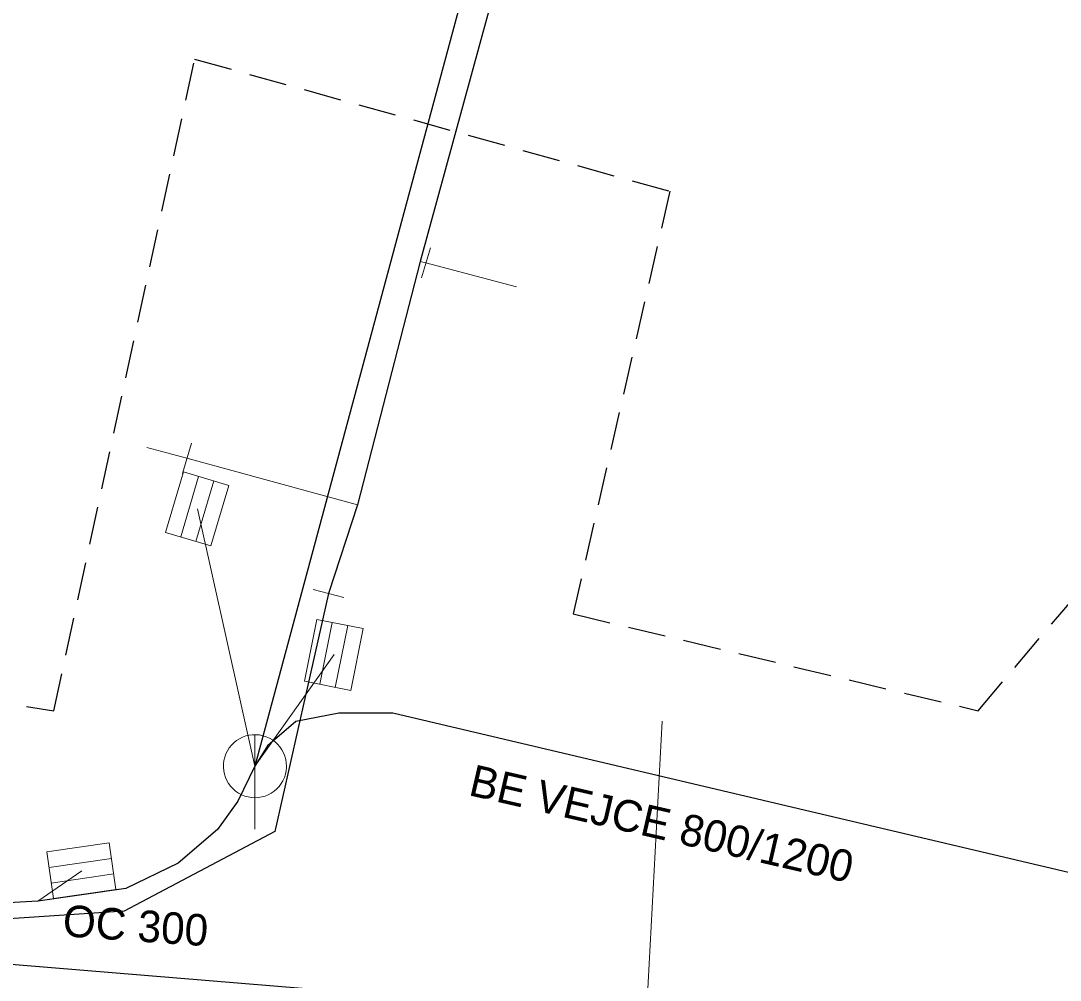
# Model space of a CAD drawing. Extents: x -725643 to -725418, y -978375 to -978221.
# Drawn here: x -725534.94 to -725501.98, y -978341.11 to -978310.7 of the extents above; entities that cross this region are included whole.
import ezdxf

# ---------------------------------------------------------------- set-up
doc = ezdxf.new("R2010")
doc.units = 0
doc.header["$LTSCALE"] = 0.4
doc.linetypes.add('MEDIUM_DASHED', pattern=[4.5, 3, -1.5])
doc.layers.add('1', color=7, linetype='Continuous')
for name, color, linetype, lineweight in [('11', 7, 'Continuous', 13), ('13', 7, 'Continuous', 13), ('14', 7, 'Continuous', 25), ('17', 7, 'Continuous', 25), ('22', 7, 'Continuous', 13), ('34', 7, 'Continuous', 13), ('63', 7, 'MEDIUM_DASHED', 25)]:
    doc.layers.add(name, color=color, linetype=linetype, lineweight=lineweight)

msp = doc.modelspace()

# ---------------------------------------------------------------- linework, layer by layer
at = {"layer": '11'}
for p, q in [((-725529.334, -978326.168), (-725527.513, -978334.331)), ((-725525.004, -978330.795), (-725527.513, -978334.331)), ((-725533.005, -978337.649), (-725534.392, -978338.607))]:
    msp.add_line(p, q, dxfattribs=at)
at = {"layer": '13'}
for p, q in [((-725522.092, -978318.376), (-725519.223, -978319.135)), ((-725529.668, -978324.571), (-725530.941, -978324.232)), ((-725524.258, -978326.048), (-725529.668, -978324.571)), ((-725515.079, -978341.78), (-725514.594, -978332.899))]:
    msp.add_line(p, q, dxfattribs=at)
at = {"layer": '14'}
msp.add_line((-725514.39, -978285.573), (-725527.514, -978334.332), dxfattribs=at)
at = {"layer": '14', "lineweight": 13}
msp.add_line((-725522.274, -978318.329), (-725522.092, -978318.376), dxfattribs=at)
at = {"layer": '14'}
for points in [[(-725527.513, -978334.331), (-725528.055, -978335.436), (-725528.703, -978336.338), (-725529.951, -978337.403), (-725531.603, -978338.206), (-725534.392, -978338.607), (-725536.813, -978338.747), (-725553.081, -978337.228), (-725592.702, -978330.168)], [(-725500.956, -978337.877), (-725523.136, -978332.647), (-725524.855, -978332.647), (-725526.213, -978332.919), (-725527.118, -978333.688), (-725527.513, -978334.331)]]:
    msp.add_lwpolyline(points, dxfattribs=at)
at = {"layer": '17'}
for points in [[(-725501.997, -978253.052), (-725503.357, -978256.875), (-725505.252, -978262.592), (-725505.556, -978263.438), (-725508.484, -978272.373), (-725509.739, -978276.131), (-725510.554, -978278.613), (-725510.695, -978279.061), (-725511.728, -978282.605), (-725512.877, -978286.761), (-725514.173, -978290.473), (-725514.784, -978292.403), (-725516.449, -978298.217), (-725517.002, -978300.824), (-725519.502, -978308.238), (-725519.585, -978308.511), (-725522.274, -978318.329), (-725524.258, -978326.048), (-725525.18, -978328.858)], [(-725525.18, -978328.858), (-725526.883, -978336.403), (-725531.655, -978338.927), (-725545.003, -978339.812)], [(-725516.432, -978342.059), (-725524.989, -978341.46), (-725545.003, -978339.812), (-725548.553, -978340.172), (-725550.989, -978339.387)]]:
    msp.add_lwpolyline(points, dxfattribs=at)
at = {"layer": '22'}
for p, q in [((-725529.865, -978327.065), (-725529.3, -978325.146)), ((-725529.386, -978327.206), (-725528.82, -978325.288)), ((-725525.453, -978331.735), (-725525.061, -978329.774)), ((-725524.963, -978331.834), (-725524.571, -978329.873)), ((-725527.513, -978336.331), (-725527.512, -978333.331)), ((-725534.042, -978337.54), (-725532.062, -978337.253)), ((-725533.97, -978338.034), (-725531.991, -978337.748))]:
    msp.add_line(p, q, dxfattribs=at)
for points in [[(-725530.345, -978326.924), (-725529.78, -978325.005), (-725528.341, -978325.429), (-725528.906, -978327.347)], [(-725525.944, -978331.637), (-725525.551, -978329.676), (-725524.08, -978329.971), (-725524.473, -978331.932)], [(-725526.513, -978334.331), (-725526.518, -978334.222), (-725526.536, -978334.114), (-725526.566, -978334.008), (-725526.606, -978333.907), (-725526.658, -978333.81), (-725526.72, -978333.72), (-725526.792, -978333.637), (-725526.872, -978333.563), (-725526.96, -978333.497), (-725527.054, -978333.442), (-725527.154, -978333.397), (-725527.259, -978333.364), (-725527.366, -978333.342), (-725527.475, -978333.332), (-725527.585, -978333.334), (-725527.693, -978333.348), (-725527.8, -978333.373), (-725527.903, -978333.41), (-725528.001, -978333.459), (-725528.093, -978333.517), (-725528.179, -978333.586), (-725528.256, -978333.663), (-725528.325, -978333.749), (-725528.384, -978333.841), (-725528.432, -978333.939), (-725528.469, -978334.042), (-725528.495, -978334.149), (-725528.509, -978334.257), (-725528.512, -978334.367), (-725528.502, -978334.476), (-725528.481, -978334.583), (-725528.447, -978334.687), (-725528.403, -978334.787), (-725528.348, -978334.882), (-725528.282, -978334.97), (-725528.208, -978335.05), (-725528.125, -978335.122), (-725528.035, -978335.184), (-725527.939, -978335.236), (-725527.837, -978335.277), (-725527.732, -978335.307), (-725527.624, -978335.325), (-725527.514, -978335.331), (-725527.405, -978335.325), (-725527.297, -978335.307), (-725527.192, -978335.278), (-725527.09, -978335.237), (-725526.993, -978335.185), (-725526.903, -978335.123), (-725526.82, -978335.052), (-725526.745, -978334.972), (-725526.68, -978334.884), (-725526.624, -978334.79), (-725526.58, -978334.69), (-725526.546, -978334.586), (-725526.524, -978334.478), (-725526.514, -978334.369)], [(-725534.113, -978337.045), (-725532.134, -978336.758), (-725531.919, -978338.243), (-725533.899, -978338.529)]]:
    msp.add_lwpolyline(points, close=True, dxfattribs=at)
at = {"layer": '34'}
for p, q in [((-725522.232, -978318.855), (-725521.95, -978317.896)), ((-725529.811, -978325.05), (-725529.523, -978324.092)), ((-725525.664, -978328.735), (-725524.695, -978328.981))]:
    msp.add_line(p, q, dxfattribs=at)
at = {"layer": '63'}
msp.add_lwpolyline([(-725440.663, -978348.762), (-725504.582, -978352.39), (-725504.582, -978352.39), (-725528.587, -978359.368), (-725528.587, -978359.368), (-725551.474, -978371.929), (-725551.474, -978371.929), (-725566.826, -978360.206), (-725566.826, -978360.206), (-725557.894, -978328.944), (-725533.89, -978332.573), (-725533.89, -978332.573), (-725529.424, -978311.918), (-725529.424, -978311.918), (-725514.351, -978316.105), (-725514.351, -978316.105), (-725517.422, -978329.502), (-725517.422, -978329.502), (-725504.582, -978332.573), (-725504.582, -978332.573), (-725495.092, -978321.408)], dxfattribs=at)

# ---------------------------------------------------------------- texts
at = {"layer": '1'}
for s, rotation, p in [('BE VEJCE 800/1200 ', 347, (-725520.774, -978335.242)), ('OC 300', 356, (-725533.63, -978339.718))]:
    msp.add_text(s, height=1, rotation=rotation, dxfattribs=at).set_placement(p)

doc.saveas('drawing.dxf')
